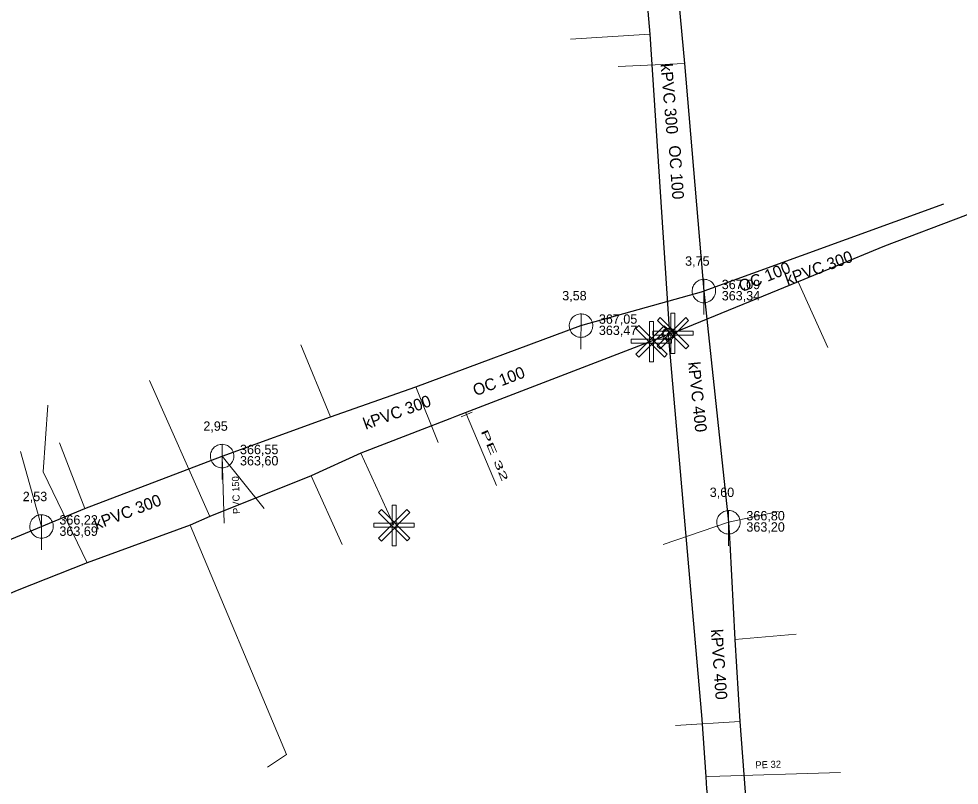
# Model space of a CAD drawing. Extents: x -809916 to -809489, y -991143 to -990912.
# Drawn here: x -809621.9 to -809541.8, y -991050.4 to -990985.1 of the extents above; entities that cross this region are included whole.
import ezdxf

# ---------------------------------------------------------------- set-up
doc = ezdxf.new("R2010")
doc.units = 0
doc.header["$LTSCALE"] = 0.32
doc.layers.add('1', color=7, linetype='Continuous')
for name, color, linetype, lineweight in [('11', 7, 'Continuous', 13), ('12', 7, 'Continuous', 13), ('13', 7, 'Continuous', 13), ('14', 7, 'Continuous', 25), ('17', 7, 'Continuous', 25), ('19', 7, 'Continuous', 13), ('22', 7, 'Continuous', 13), ('34', 7, 'Continuous', 13), ('47', 7, 'Continuous', 13)]:
    doc.layers.add(name, color=color, linetype=linetype, lineweight=lineweight)

msp = doc.modelspace()

# ---------------------------------------------------------------- linework, layer by layer
at = {"layer": '11'}
for p, q in [((-809570.868, -990989.151), (-809565.206, -990988.914)), ((-809597.875, -991012.848), (-809595.351, -991018.99)), ((-809586.188, -991021.175), (-809588.078, -991016.434)), ((-809618.448, -991021.201), (-809616.286, -991026.804)), ((-809621.763, -991021.954), (-809619.972, -991028.327)), ((-809601.02, -991026.795), (-809604.59, -991022.332)), ((-809604.425, -991028.055), (-809604.59, -991022.332)), ((-809557.21, -991027.06), (-809561.458, -991027.97)), ((-809567.01, -991029.872), (-809561.458, -991027.97)), ((-809555.706, -991037.513), (-809560.919, -991037.951)), ((-809565.967, -991045.287), (-809560.48, -991044.932))]:
    msp.add_line(p, q, dxfattribs=at)
at = {"layer": '12'}
for points in [[(-809566.367, -991010.174), (-809566.017, -991010.174), (-809566.017, -991013.609), (-809566.367, -991013.609)], [(-809568.194, -991010.869), (-809567.843, -991010.869), (-809567.843, -991014.304), (-809568.194, -991014.304)], [(-809565.101, -991010.538), (-809564.853, -991010.786), (-809567.282, -991013.215), (-809567.529, -991012.967)], [(-809567.52, -991010.777), (-809567.273, -991010.529), (-809564.844, -991012.958), (-809565.091, -991013.206)], [(-809566.928, -991011.233), (-809566.679, -991011.481), (-809569.108, -991013.91), (-809569.355, -991013.662)], [(-809569.347, -991011.472), (-809569.1, -991011.224), (-809566.671, -991013.653), (-809566.918, -991013.901)], [(-809564.483, -991011.683), (-809564.483, -991012.033), (-809567.918, -991012.033), (-809567.918, -991011.683)], [(-809566.309, -991012.378), (-809566.309, -991012.728), (-809569.745, -991012.728), (-809569.745, -991012.378)], [(-809588.845, -991026.892), (-809588.597, -991027.14), (-809591.026, -991029.569), (-809591.272, -991029.321)], [(-809591.264, -991027.131), (-809591.017, -991026.883), (-809588.588, -991029.312), (-809588.835, -991029.56)], [(-809590.111, -991026.528), (-809589.761, -991026.528), (-809589.761, -991029.963), (-809590.111, -991029.963)], [(-809588.227, -991028.037), (-809588.227, -991028.387), (-809591.662, -991028.387), (-809591.662, -991028.037)]]:
    msp.add_lwpolyline(points, close=True, dxfattribs=at)
at = {"layer": '13'}
for p, q in [((-809568.171, -990986.399), (-809574.925, -990986.824)), ((-809555.532, -991007.487), (-809552.992, -991013.099)), ((-809605.641, -991027.483), (-809610.785, -991015.899)), ((-809583.765, -991018.794), (-809581.219, -991024.83)), ((-809592.769, -991022.094), (-809589.954, -991028.213)), ((-809597.001, -991024.014), (-809594.355, -991029.872))]:
    msp.add_line(p, q, dxfattribs=at)
for points in [[(-809616.081, -991031.412), (-809619.832, -991023.679), (-809619.432, -991018.012)], [(-809607.317, -991028.216), (-809599.116, -991047.753), (-809600.719, -991048.835)], [(-809563.364, -991049.635), (-809563.138, -991049.607), (-809551.918, -991049.27)]]:
    msp.add_lwpolyline(points, dxfattribs=at)
at = {"layer": '14'}
msp.add_line((-809543.143, -991000.876), (-809563.556, -991008.277), dxfattribs=at)
at = {"layer": '14', "lineweight": 13}
for p, q in [((-809566.593, -991011.958), (-809566.209, -991011.859)), ((-809566.909, -991012.119), (-809566.593, -991011.958)), ((-809583.827, -991018.638), (-809583.765, -991018.794))]:
    msp.add_line(p, q, dxfattribs=at)
at = {"layer": '14'}
for points in [[(-809566.299, -990977.262), (-809565.206, -990988.914), (-809563.556, -991008.277), (-809561.458, -991027.97)], [(-809604.59, -991022.332), (-809595.351, -991018.99), (-809588.078, -991016.434), (-809574.023, -991011.225), (-809563.556, -991008.277)], [(-809619.972, -991028.327), (-809616.286, -991026.804), (-809604.59, -991022.332)], [(-809645.575, -991038.5), (-809627.638, -991031.374), (-809623.903, -991029.949), (-809619.972, -991028.327)], [(-809561.458, -991027.97), (-809561.357, -991029.791), (-809560.919, -991037.951), (-809560.48, -991044.932), (-809559.806, -991053.969), (-809558.548, -991079.472)]]:
    msp.add_lwpolyline(points, dxfattribs=at)
at = {"layer": '14', "lineweight": 13}
msp.add_lwpolyline([(-809566.549, -991012.279), (-809566.593, -991011.958), (-809566.509, -991011.539)], dxfattribs=at)
at = {"layer": '17'}
for points in [[(-809570.963, -990948.696), (-809570.888, -990951.155), (-809570.151, -990960.84), (-809569.46, -990971.101), (-809569.015, -990975.975), (-809568.635, -990980.85), (-809568.171, -990986.399), (-809566.509, -991011.539)], [(-809530.654, -990997.331), (-809541.087, -991001.769), (-809541.272, -991001.848), (-809548.182, -991004.471), (-809548.653, -991004.666), (-809555.532, -991007.487), (-809566.209, -991011.859)], [(-809566.909, -991012.119), (-809584.614, -991018.942), (-809585.199, -991019.149), (-809592.769, -991022.094), (-809597, -991024.013), (-809605.64, -991027.482), (-809607.317, -991028.215), (-809616.081, -991031.412), (-809622.052, -991033.77), (-809631.921, -991038.028), (-809637.348, -991039.71), (-809639.388, -991040.574), (-809651.392, -991045.594), (-809661.144, -991049.477), (-809662.639, -991050.049)], [(-809557.019, -991142.819), (-809557.113, -991139.333), (-809557.276, -991137.739), (-809557.363, -991136.19), (-809563.12, -991056.625), (-809563.21, -991051.333), (-809563.298, -991050.671), (-809563.364, -991049.635), (-809563.695, -991044.738), (-809566.549, -991012.279)]]:
    msp.add_lwpolyline(points, dxfattribs=at)
at = {"layer": '22'}
for p, q in [((-809563.556, -991010.277), (-809563.555, -991007.277)), ((-809574.023, -991013.225), (-809574.022, -991010.225)), ((-809604.59, -991024.332), (-809604.589, -991021.332)), ((-809561.458, -991029.97), (-809561.457, -991026.97)), ((-809619.972, -991030.327), (-809619.971, -991027.327))]:
    msp.add_line(p, q, dxfattribs=at)
for points in [[(-809562.556, -991008.277), (-809562.561, -991008.168), (-809562.579, -991008.06), (-809562.609, -991007.954), (-809562.649, -991007.853), (-809562.701, -991007.756), (-809562.763, -991007.666), (-809562.835, -991007.583), (-809562.915, -991007.509), (-809563.003, -991007.443), (-809563.097, -991007.388), (-809563.197, -991007.343), (-809563.302, -991007.31), (-809563.409, -991007.288), (-809563.518, -991007.278), (-809563.628, -991007.28), (-809563.736, -991007.294), (-809563.843, -991007.319), (-809563.946, -991007.356), (-809564.044, -991007.405), (-809564.136, -991007.463), (-809564.222, -991007.532), (-809564.299, -991007.609), (-809564.368, -991007.695), (-809564.427, -991007.787), (-809564.475, -991007.885), (-809564.512, -991007.988), (-809564.538, -991008.095), (-809564.552, -991008.203), (-809564.555, -991008.313), (-809564.545, -991008.422), (-809564.524, -991008.529), (-809564.49, -991008.633), (-809564.446, -991008.733), (-809564.391, -991008.828), (-809564.325, -991008.916), (-809564.251, -991008.996), (-809564.168, -991009.068), (-809564.078, -991009.13), (-809563.982, -991009.182), (-809563.88, -991009.223), (-809563.775, -991009.253), (-809563.667, -991009.271), (-809563.557, -991009.277), (-809563.448, -991009.271), (-809563.34, -991009.253), (-809563.235, -991009.224), (-809563.133, -991009.183), (-809563.036, -991009.131), (-809562.946, -991009.069), (-809562.863, -991008.998), (-809562.788, -991008.918), (-809562.723, -991008.83), (-809562.667, -991008.736), (-809562.623, -991008.636), (-809562.589, -991008.532), (-809562.567, -991008.424), (-809562.557, -991008.315)], [(-809573.023, -991011.225), (-809573.028, -991011.116), (-809573.046, -991011.008), (-809573.076, -991010.902), (-809573.116, -991010.801), (-809573.168, -991010.704), (-809573.23, -991010.614), (-809573.302, -991010.531), (-809573.382, -991010.457), (-809573.47, -991010.391), (-809573.564, -991010.336), (-809573.664, -991010.291), (-809573.769, -991010.258), (-809573.876, -991010.236), (-809573.985, -991010.226), (-809574.095, -991010.228), (-809574.203, -991010.242), (-809574.31, -991010.267), (-809574.413, -991010.304), (-809574.511, -991010.353), (-809574.603, -991010.411), (-809574.689, -991010.48), (-809574.766, -991010.557), (-809574.835, -991010.643), (-809574.894, -991010.735), (-809574.942, -991010.833), (-809574.979, -991010.936), (-809575.005, -991011.043), (-809575.019, -991011.151), (-809575.022, -991011.261), (-809575.012, -991011.37), (-809574.991, -991011.477), (-809574.957, -991011.581), (-809574.913, -991011.681), (-809574.858, -991011.776), (-809574.792, -991011.864), (-809574.718, -991011.944), (-809574.635, -991012.016), (-809574.545, -991012.078), (-809574.449, -991012.13), (-809574.347, -991012.171), (-809574.242, -991012.201), (-809574.134, -991012.219), (-809574.024, -991012.225), (-809573.915, -991012.219), (-809573.807, -991012.201), (-809573.702, -991012.172), (-809573.6, -991012.131), (-809573.503, -991012.079), (-809573.413, -991012.017), (-809573.33, -991011.946), (-809573.255, -991011.866), (-809573.19, -991011.778), (-809573.134, -991011.684), (-809573.09, -991011.584), (-809573.056, -991011.48), (-809573.034, -991011.372), (-809573.024, -991011.263)], [(-809603.59, -991022.332), (-809603.595, -991022.223), (-809603.613, -991022.115), (-809603.643, -991022.009), (-809603.683, -991021.908), (-809603.735, -991021.811), (-809603.797, -991021.721), (-809603.869, -991021.638), (-809603.949, -991021.564), (-809604.037, -991021.498), (-809604.131, -991021.443), (-809604.231, -991021.398), (-809604.336, -991021.365), (-809604.443, -991021.343), (-809604.552, -991021.333), (-809604.662, -991021.335), (-809604.77, -991021.349), (-809604.877, -991021.374), (-809604.98, -991021.411), (-809605.078, -991021.46), (-809605.17, -991021.518), (-809605.256, -991021.587), (-809605.333, -991021.664), (-809605.402, -991021.75), (-809605.461, -991021.842), (-809605.509, -991021.94), (-809605.546, -991022.043), (-809605.572, -991022.15), (-809605.586, -991022.258), (-809605.589, -991022.368), (-809605.579, -991022.477), (-809605.558, -991022.584), (-809605.524, -991022.688), (-809605.48, -991022.788), (-809605.425, -991022.883), (-809605.359, -991022.971), (-809605.285, -991023.051), (-809605.202, -991023.123), (-809605.112, -991023.185), (-809605.016, -991023.237), (-809604.914, -991023.278), (-809604.809, -991023.308), (-809604.701, -991023.326), (-809604.591, -991023.332), (-809604.482, -991023.326), (-809604.374, -991023.308), (-809604.269, -991023.279), (-809604.167, -991023.238), (-809604.07, -991023.186), (-809603.98, -991023.124), (-809603.897, -991023.053), (-809603.822, -991022.973), (-809603.757, -991022.885), (-809603.701, -991022.791), (-809603.657, -991022.691), (-809603.623, -991022.587), (-809603.601, -991022.479), (-809603.591, -991022.37)], [(-809560.458, -991027.97), (-809560.463, -991027.861), (-809560.481, -991027.753), (-809560.511, -991027.647), (-809560.551, -991027.546), (-809560.603, -991027.449), (-809560.665, -991027.359), (-809560.737, -991027.276), (-809560.817, -991027.202), (-809560.905, -991027.136), (-809560.999, -991027.081), (-809561.099, -991027.036), (-809561.204, -991027.003), (-809561.311, -991026.981), (-809561.42, -991026.971), (-809561.53, -991026.973), (-809561.638, -991026.987), (-809561.745, -991027.012), (-809561.848, -991027.049), (-809561.946, -991027.098), (-809562.038, -991027.156), (-809562.124, -991027.225), (-809562.201, -991027.302), (-809562.27, -991027.388), (-809562.329, -991027.48), (-809562.377, -991027.578), (-809562.414, -991027.681), (-809562.44, -991027.788), (-809562.454, -991027.896), (-809562.457, -991028.006), (-809562.447, -991028.115), (-809562.426, -991028.222), (-809562.392, -991028.326), (-809562.348, -991028.426), (-809562.293, -991028.521), (-809562.227, -991028.609), (-809562.153, -991028.689), (-809562.07, -991028.761), (-809561.98, -991028.823), (-809561.884, -991028.875), (-809561.782, -991028.916), (-809561.677, -991028.946), (-809561.569, -991028.964), (-809561.459, -991028.97), (-809561.35, -991028.964), (-809561.242, -991028.946), (-809561.137, -991028.917), (-809561.035, -991028.876), (-809560.938, -991028.824), (-809560.848, -991028.762), (-809560.765, -991028.691), (-809560.69, -991028.611), (-809560.625, -991028.523), (-809560.569, -991028.429), (-809560.525, -991028.329), (-809560.491, -991028.225), (-809560.469, -991028.117), (-809560.459, -991028.008)], [(-809618.972, -991028.327), (-809618.977, -991028.218), (-809618.995, -991028.11), (-809619.025, -991028.004), (-809619.065, -991027.903), (-809619.117, -991027.806), (-809619.179, -991027.716), (-809619.251, -991027.633), (-809619.331, -991027.559), (-809619.419, -991027.493), (-809619.513, -991027.438), (-809619.613, -991027.393), (-809619.718, -991027.36), (-809619.825, -991027.338), (-809619.934, -991027.328), (-809620.044, -991027.33), (-809620.152, -991027.344), (-809620.259, -991027.369), (-809620.362, -991027.406), (-809620.46, -991027.455), (-809620.552, -991027.513), (-809620.638, -991027.582), (-809620.715, -991027.659), (-809620.784, -991027.745), (-809620.843, -991027.837), (-809620.891, -991027.935), (-809620.928, -991028.038), (-809620.954, -991028.145), (-809620.968, -991028.253), (-809620.971, -991028.363), (-809620.961, -991028.472), (-809620.94, -991028.579), (-809620.906, -991028.683), (-809620.862, -991028.783), (-809620.807, -991028.878), (-809620.741, -991028.966), (-809620.667, -991029.046), (-809620.584, -991029.118), (-809620.494, -991029.18), (-809620.398, -991029.232), (-809620.296, -991029.273), (-809620.191, -991029.303), (-809620.083, -991029.321), (-809619.973, -991029.327), (-809619.864, -991029.321), (-809619.756, -991029.303), (-809619.651, -991029.274), (-809619.549, -991029.233), (-809619.452, -991029.181), (-809619.362, -991029.119), (-809619.279, -991029.048), (-809619.204, -991028.968), (-809619.139, -991028.88), (-809619.083, -991028.786), (-809619.039, -991028.686), (-809619.005, -991028.582), (-809618.983, -991028.474), (-809618.973, -991028.365)]]:
    msp.add_lwpolyline(points, close=True, dxfattribs=at)
at = {"layer": '34'}
for p, q in [((-809567.102, -991011.658), (-809566.716, -991012.58)), ((-809566.011, -991011.49), (-809567.006, -991011.586)), ((-809566.402, -991011.398), (-809566.016, -991012.32)), ((-809566.051, -991012.23), (-809567.046, -991012.326)), ((-809583.301, -991018.607), (-809584.229, -991018.98))]:
    msp.add_line(p, q, dxfattribs=at)
at = {"layer": '47'}
for points in [[(-809566.404, -991012.42), (-809566.357, -991012.398), (-809566.312, -991012.371), (-809566.271, -991012.339), (-809566.232, -991012.304), (-809566.197, -991012.264), (-809566.168, -991012.221), (-809566.143, -991012.175), (-809566.123, -991012.127), (-809566.107, -991012.077), (-809566.097, -991012.025), (-809566.093, -991011.973), (-809566.095, -991011.921), (-809566.1, -991011.869), (-809566.113, -991011.818), (-809566.13, -991011.769), (-809566.152, -991011.722), (-809566.179, -991011.677), (-809566.211, -991011.635), (-809566.246, -991011.597), (-809566.286, -991011.562), (-809566.329, -991011.533), (-809566.375, -991011.507), (-809566.424, -991011.487), (-809566.473, -991011.471), (-809566.525, -991011.462), (-809566.577, -991011.458), (-809566.63, -991011.459), (-809566.681, -991011.465), (-809566.732, -991011.478), (-809566.781, -991011.495), (-809566.828, -991011.517), (-809566.873, -991011.544), (-809566.916, -991011.575), (-809566.953, -991011.611), (-809566.988, -991011.651), (-809567.018, -991011.694), (-809567.043, -991011.74), (-809567.063, -991011.788), (-809567.079, -991011.838), (-809567.088, -991011.89), (-809567.092, -991011.942), (-809567.092, -991011.994), (-809567.085, -991012.046), (-809567.072, -991012.097), (-809567.055, -991012.146), (-809567.033, -991012.193), (-809567.006, -991012.238), (-809566.975, -991012.28), (-809566.939, -991012.318), (-809566.899, -991012.353), (-809566.856, -991012.383), (-809566.811, -991012.407), (-809566.763, -991012.428), (-809566.712, -991012.443), (-809566.66, -991012.453), (-809566.608, -991012.457), (-809566.557, -991012.456), (-809566.504, -991012.45), (-809566.453, -991012.437)], [(-809566.562, -991012.033), (-809566.553, -991012.03), (-809566.547, -991012.025), (-809566.54, -991012.02), (-809566.534, -991012.014), (-809566.528, -991012.008), (-809566.523, -991012), (-809566.519, -991011.993), (-809566.515, -991011.985), (-809566.513, -991011.977), (-809566.511, -991011.969), (-809566.511, -991011.96), (-809566.511, -991011.951), (-809566.512, -991011.943), (-809566.513, -991011.935), (-809566.517, -991011.927), (-809566.52, -991011.918), (-809566.525, -991011.912), (-809566.53, -991011.905), (-809566.536, -991011.899), (-809566.542, -991011.893), (-809566.55, -991011.888), (-809566.557, -991011.884), (-809566.565, -991011.88), (-809566.573, -991011.877), (-809566.581, -991011.876), (-809566.59, -991011.876), (-809566.599, -991011.876), (-809566.607, -991011.877), (-809566.615, -991011.878), (-809566.623, -991011.882), (-809566.632, -991011.885), (-809566.638, -991011.89), (-809566.645, -991011.895), (-809566.651, -991011.901), (-809566.657, -991011.907), (-809566.662, -991011.914), (-809566.666, -991011.922), (-809566.67, -991011.93), (-809566.673, -991011.938), (-809566.674, -991011.946), (-809566.674, -991011.955), (-809566.674, -991011.964), (-809566.673, -991011.972), (-809566.672, -991011.98), (-809566.668, -991011.988), (-809566.665, -991011.997), (-809566.66, -991012.003), (-809566.655, -991012.01), (-809566.649, -991012.016), (-809566.643, -991012.022), (-809566.636, -991012.027), (-809566.628, -991012.031), (-809566.62, -991012.035), (-809566.612, -991012.037), (-809566.604, -991012.039), (-809566.595, -991012.039), (-809566.586, -991012.039), (-809566.578, -991012.038), (-809566.57, -991012.037)]]:
    msp.add_lwpolyline(points, close=True, dxfattribs=at)

# ---------------------------------------------------------------- texts
at = {"layer": '1'}
for s, height, rotation, p in [('kPVC 300', 1, 275, (-809567.257, -990988.959)), ('OC 100', 1, 274, (-809566.554, -990995.91)), ('kPVC 300', 1, 20, (-809556.433, -991007.806)), ('OC 100', 1, 22, (-809560.345, -991008.39)), ('OC 100', 1, 21, (-809583, -991017.245)), ('kPVC 400', 1, 276, (-809564.904, -991014.356)), ('kPVC 300', 1, 20, (-809592.355, -991020.1)), ('PVC 150 ', 0.6, 92, (-809603.056, -991027.252)), ('kPVC 300', 1, 21, (-809615.287, -991028.631)), ('kPVC 400', 1, 274, (-809562.966, -991037.109)), ('PE 32 ', 0.6, 2, (-809559.157, -991048.938))]:
    msp.add_text(s, height=height, rotation=rotation, dxfattribs=at).set_placement(p)
for s, p in [('3,75', (-809565.156, -991006.125)), ('3,58', (-809575.623, -991009.073)), ('2,95', (-809606.19, -991020.18)), ('2,53', (-809621.572, -991026.175)), ('3,60', (-809563.058, -991025.818))]:
    msp.add_text(s, height=0.8, dxfattribs=at).set_placement(p)
at = {"layer": '1', "width": 2.15}
msp.add_text('PE 32 ', height=0.6, rotation=293, dxfattribs=at).set_placement((-809582.576, -991020.219))
at = {"layer": '19'}
for s, p in [('367,09', (-809562.034, -991008.117)), ('363,34', (-809562.034, -991009.077)), ('367,05', (-809572.501, -991011.065)), ('363,47', (-809572.501, -991012.025)), ('366,55', (-809603.068, -991022.172)), ('363,60', (-809603.068, -991023.132)), ('366,80', (-809559.936, -991027.81)), ('366,22', (-809618.45, -991028.167)), ('363,69', (-809618.45, -991029.127)), ('363,20', (-809559.936, -991028.77))]:
    msp.add_text(s, height=0.8, dxfattribs=at).set_placement(p)

doc.saveas('drawing.dxf')
